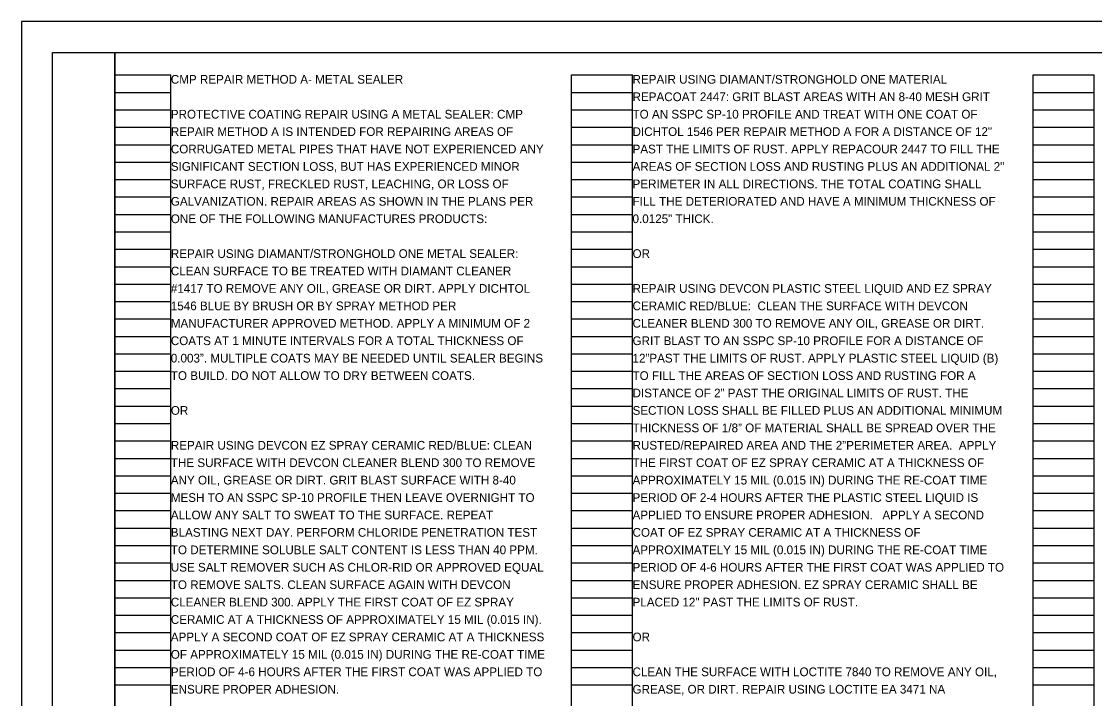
# Model space of a CAD drawing. Extents: x 0 to 34, y -22.7 to 22.
# Drawn here: x 0 to 17.24, y 11.12 to 22 of the extents above; entities that cross this region are included whole.
import ezdxf

# ---------------------------------------------------------------- set-up
doc = ezdxf.new("R2010")
doc.units = 0
for name, color, linetype in [('SH_Border', 7, 'Continuous'), ('SH_Cut_Line', 7, 'Continuous'), ('SH_Data', 7, 'Continuous'), ('SH_Text', 7, 'Continuous')]:
    doc.layers.add(name, color=color, linetype=linetype)

msp = doc.modelspace()

# ---------------------------------------------------------------- linework, layer by layer
at = {"layer": 'SH_Border'}
for points in [[(0.5, 21.5), (1.5, 21.5), (1.5, 0.5), (0.5, 0.5)], [(1.5, 21.5), (33.5, 21.5), (33.5, 0.5), (1.5, 0.5)]]:
    msp.add_lwpolyline(points, close=True, dxfattribs=at)
at = {"layer": 'SH_Cut_Line'}
msp.add_lwpolyline([(0, 0), (34, 0), (34, 22), (0, 22)], close=True, dxfattribs=at)
at = {"layer": 'SH_Data'}
for p, q in [((1.5, 0.98), (1.5, 21.14)), ((1.5, 21.14), (2.4, 21.14)), ((2.4, 0.98), (2.4, 21.14)), ((8.84, 0.98), (8.84, 21.14)), ((8.84, 21.14), (9.82, 21.14)), ((9.82, 0.98), (9.82, 21.14)), ((16.26, 0.98), (16.26, 21.14)), ((16.26, 21.14), (17.24, 21.14)), ((17.24, 0.98), (17.24, 21.14)), ((1.5, 20.86), (2.4, 20.86)), ((8.84, 20.86), (9.82, 20.86)), ((16.26, 20.86), (17.24, 20.86)), ((1.5, 20.58), (2.4, 20.58)), ((8.84, 20.58), (9.82, 20.58)), ((16.26, 20.58), (17.24, 20.58)), ((1.5, 20.3), (2.4, 20.3)), ((8.84, 20.3), (9.82, 20.3)), ((16.26, 20.3), (17.24, 20.3)), ((1.5, 20.02), (2.4, 20.02)), ((8.84, 20.02), (9.82, 20.02)), ((16.26, 20.02), (17.24, 20.02)), ((1.5, 19.74), (2.4, 19.74)), ((8.84, 19.74), (9.82, 19.74)), ((16.26, 19.74), (17.24, 19.74)), ((1.5, 19.46), (2.4, 19.46)), ((8.84, 19.46), (9.82, 19.46)), ((16.26, 19.46), (17.24, 19.46)), ((1.5, 19.18), (2.4, 19.18)), ((8.84, 19.18), (9.82, 19.18)), ((16.26, 19.18), (17.24, 19.18)), ((1.5, 18.9), (2.4, 18.9)), ((8.84, 18.9), (9.82, 18.9)), ((16.26, 18.9), (17.24, 18.9)), ((1.5, 18.62), (2.4, 18.62)), ((8.84, 18.62), (9.82, 18.62)), ((16.26, 18.62), (17.24, 18.62)), ((1.5, 18.34), (2.4, 18.34)), ((8.84, 18.34), (9.82, 18.34)), ((16.26, 18.34), (17.24, 18.34)), ((1.5, 18.06), (2.4, 18.06)), ((8.84, 18.06), (9.82, 18.06)), ((16.26, 18.06), (17.24, 18.06)), ((1.5, 17.78), (2.4, 17.78)), ((8.84, 17.78), (9.82, 17.78)), ((16.26, 17.78), (17.24, 17.78)), ((1.5, 17.5), (2.4, 17.5)), ((8.84, 17.5), (9.82, 17.5)), ((16.26, 17.5), (17.24, 17.5)), ((1.5, 17.22), (2.4, 17.22)), ((8.84, 17.22), (9.82, 17.22)), ((16.26, 17.22), (17.24, 17.22)), ((1.5, 16.94), (2.4, 16.94)), ((8.84, 16.94), (9.82, 16.94)), ((16.26, 16.94), (17.24, 16.94)), ((1.5, 16.66), (2.4, 16.66)), ((8.84, 16.66), (9.82, 16.66)), ((16.26, 16.66), (17.24, 16.66)), ((1.5, 16.38), (2.4, 16.38)), ((8.84, 16.38), (9.82, 16.38)), ((16.26, 16.38), (17.24, 16.38)), ((1.5, 16.1), (2.4, 16.1)), ((8.84, 16.1), (9.82, 16.1)), ((16.26, 16.1), (17.24, 16.1)), ((1.5, 15.82), (2.4, 15.82)), ((8.84, 15.82), (9.82, 15.82)), ((16.26, 15.82), (17.24, 15.82)), ((1.5, 15.54), (2.4, 15.54)), ((8.84, 15.54), (9.82, 15.54)), ((16.26, 15.54), (17.24, 15.54)), ((1.5, 15.26), (2.4, 15.26)), ((8.84, 15.26), (9.82, 15.26)), ((16.26, 15.26), (17.24, 15.26)), ((1.5, 14.98), (2.4, 14.98)), ((8.84, 14.98), (9.82, 14.98)), ((16.26, 14.98), (17.24, 14.98)), ((1.5, 14.7), (2.4, 14.7)), ((8.84, 14.7), (9.82, 14.7)), ((16.26, 14.7), (17.24, 14.7)), ((1.5, 14.42), (2.4, 14.42)), ((8.84, 14.42), (9.82, 14.42)), ((16.26, 14.42), (17.24, 14.42)), ((1.5, 14.14), (2.4, 14.14)), ((8.84, 14.14), (9.82, 14.14)), ((16.26, 14.14), (17.24, 14.14)), ((1.5, 13.86), (2.4, 13.86)), ((8.84, 13.86), (9.82, 13.86)), ((16.26, 13.86), (17.24, 13.86)), ((1.5, 13.58), (2.4, 13.58)), ((8.84, 13.58), (9.82, 13.58)), ((16.26, 13.58), (17.24, 13.58)), ((1.5, 13.3), (2.4, 13.3)), ((8.84, 13.3), (9.82, 13.3)), ((16.26, 13.3), (17.24, 13.3)), ((1.5, 13.02), (2.4, 13.02)), ((8.84, 13.02), (9.82, 13.02)), ((16.26, 13.02), (17.24, 13.02)), ((1.5, 12.74), (2.4, 12.74)), ((8.84, 12.74), (9.82, 12.74)), ((16.26, 12.74), (17.24, 12.74)), ((1.5, 12.46), (2.4, 12.46)), ((8.84, 12.46), (9.82, 12.46)), ((16.26, 12.46), (17.24, 12.46)), ((1.5, 12.18), (2.4, 12.18)), ((8.84, 12.18), (9.82, 12.18)), ((16.26, 12.18), (17.24, 12.18)), ((1.5, 11.9), (2.4, 11.9)), ((8.84, 11.9), (9.82, 11.9)), ((16.26, 11.9), (17.24, 11.9)), ((1.5, 11.62), (2.4, 11.62)), ((8.84, 11.62), (9.82, 11.62)), ((16.26, 11.62), (17.24, 11.62)), ((1.5, 11.34), (2.4, 11.34)), ((8.84, 11.34), (9.82, 11.34)), ((16.26, 11.34), (17.24, 11.34))]:
    msp.add_line(p, q, dxfattribs=at)

# ---------------------------------------------------------------- texts
at = {"layer": 'SH_Text'}
for s, p in [('CMP REPAIR METHOD A- METAL SEALER', (2.4, 21)), ('REPAIR USING DIAMANT/STRONGHOLD ONE MATERIAL ', (9.82, 21)), ('REPACOAT 2447: GRIT BLAST AREAS WITH AN 8-40 MESH GRIT ', (9.82, 20.72)), ('PROTECTIVE COATING REPAIR USING A METAL SEALER: CMP ', (2.4, 20.44)), ('TO AN SSPC SP-10 PROFILE AND TREAT WITH ONE COAT OF ', (9.82, 20.44)), ('REPAIR METHOD A IS INTENDED FOR REPAIRING AREAS OF ', (2.4, 20.16)), ('DICHTOL 1546 PER REPAIR METHOD A FOR A DISTANCE OF 12" ', (9.82, 20.16)), ('CORRUGATED METAL PIPES THAT HAVE NOT EXPERIENCED ANY ', (2.4, 19.88)), ('PAST THE LIMITS OF RUST. APPLY REPACOUR 2447 TO FILL THE ', (9.82, 19.88)), ('SIGNIFICANT SECTION LOSS, BUT HAS EXPERIENCED MINOR ', (2.4, 19.6)), ('AREAS OF SECTION LOSS AND RUSTING PLUS AN ADDITIONAL 2" ', (9.82, 19.6)), ('SURFACE RUST, FRECKLED RUST, LEACHING, OR LOSS OF ', (2.4, 19.32)), ('PERIMETER IN ALL DIRECTIONS. THE TOTAL COATING SHALL ', (9.82, 19.32)), ('GALVANIZATION. REPAIR AREAS AS SHOWN IN THE PLANS PER ', (2.4, 19.04)), ('FILL THE DETERIORATED AND HAVE A MINIMUM THICKNESS OF ', (9.82, 19.04)), ('ONE OF THE FOLLOWING MANUFACTURES PRODUCTS:', (2.4, 18.76)), ('0.0125" THICK.', (9.82, 18.76)), ('REPAIR USING DIAMANT/STRONGHOLD ONE METAL SEALER: ', (2.4, 18.2)), ('OR', (9.82, 18.2)), ('CLEAN SURFACE TO BE TREATED WITH DIAMANT CLEANER ', (2.4, 17.92)), ('#1417 TO REMOVE ANY OIL, GREASE OR DIRT. APPLY DICHTOL ', (2.4, 17.64)), ('REPAIR USING DEVCON PLASTIC STEEL LIQUID AND EZ SPRAY ', (9.82, 17.64)), ('1546 BLUE BY BRUSH OR BY SPRAY METHOD PER ', (2.4, 17.36)), ('CERAMIC RED/BLUE: \xa0CLEAN THE SURFACE WITH DEVCON ', (9.82, 17.36)), ('MANUFACTURER APPROVED METHOD. APPLY A MINIMUM OF 2 ', (2.4, 17.08)), ('CLEANER BLEND 300 TO REMOVE ANY OIL, GREASE OR DIRT.\xa0', (9.82, 17.08)), ('COATS AT 1 MINUTE INTERVALS FOR A TOTAL THICKNESS OF ', (2.4, 16.8)), ('GRIT BLAST TO AN SSPC SP-10 PROFILE FOR A DISTANCE OF ', (9.82, 16.8)), ('0.003”. MULTIPLE COATS MAY BE NEEDED UNTIL SEALER BEGINS ', (2.4, 16.52)), ('12”PAST THE LIMITS OF RUST. APPLY\xa0PLASTIC STEEL LIQUID (B)\xa0', (9.82, 16.52)), ('TO BUILD. DO NOT ALLOW TO DRY BETWEEN COATS. ', (2.4, 16.24)), ('TO FILL THE AREAS OF SECTION LOSS AND RUSTING FOR A ', (9.82, 16.24)), ('DISTANCE OF 2” PAST THE ORIGINAL LIMITS OF RUST. THE ', (9.82, 15.96)), ('OR', (2.4, 15.68)), ('SECTION LOSS SHALL BE FILLED PLUS AN ADDITIONAL MINIMUM ', (9.82, 15.68)), ('THICKNESS OF\xa01/8”\xa0OF MATERIAL SHALL BE SPREAD OVER THE ', (9.82, 15.4)), ('REPAIR USING DEVCON EZ SPRAY CERAMIC RED/BLUE: CLEAN ', (2.4, 15.12)), ('RUSTED/REPAIRED AREA AND THE 2”PERIMETER AREA. \xa0APPLY ', (9.82, 15.12)), ('THE SURFACE WITH DEVCON CLEANER BLEND 300 TO REMOVE ', (2.4, 14.84)), ('THE FIRST COAT OF\xa0EZ SPRAY CERAMIC AT A THICKNESS OF ', (9.82, 14.84)), ('ANY OIL, GREASE OR DIRT. GRIT BLAST SURFACE WITH 8-40 ', (2.4, 14.56)), ('APPROXIMATELY 15 MIL (0.015 IN) DURING THE RE-COAT TIME ', (9.82, 14.56)), ('MESH TO AN SSPC SP-10 PROFILE THEN LEAVE OVERNIGHT TO ', (2.4, 14.28)), ('PERIOD\xa0OF 2-4 HOURS\xa0AFTER\xa0THE PLASTIC STEEL LIQUID IS ', (9.82, 14.28)), ('ALLOW ANY SALT TO SWEAT TO THE SURFACE. REPEAT ', (2.4, 14)), ('APPLIED TO ENSURE PROPER ADHESION.\xa0 \xa0APPLY A SECOND ', (9.82, 14)), ('BLASTING NEXT DAY. PERFORM CHLORIDE PENETRATION TEST ', (2.4, 13.72)), ('COAT OF EZ SPRAY CERAMIC AT A THICKNESS OF ', (9.82, 13.72)), ('TO DETERMINE SOLUBLE SALT CONTENT IS LESS THAN 40 PPM. ', (2.4, 13.44)), ('APPROXIMATELY 15 MIL (0.015 IN) DURING THE\xa0RE-COAT\xa0TIME ', (9.82, 13.44)), ('USE SALT REMOVER SUCH AS CHLOR-RID OR APPROVED EQUAL ', (2.4, 13.16)), ('PERIOD OF 4-6 HOURS AFTER THE FIRST COAT WAS APPLIED TO ', (9.82, 13.16)), ('TO REMOVE SALTS. CLEAN SURFACE AGAIN WITH DEVCON ', (2.4, 12.88)), ('ENSURE PROPER ADHESION. EZ SPRAY CERAMIC SHALL BE ', (9.82, 12.88)), ('CLEANER BLEND 300.\xa0APPLY THE FIRST COAT OF\xa0EZ SPRAY ', (2.4, 12.6)), ('PLACED 12" PAST THE LIMITS OF RUST.', (9.82, 12.6)), ('CERAMIC AT A THICKNESS OF APPROXIMATELY 15 MIL (0.015 IN). \xa0', (2.4, 12.32)), ('APPLY A SECOND COAT OF EZ SPRAY CERAMIC AT A THICKNESS ', (2.4, 12.04)), ('OR', (9.82, 12.04)), ('OF APPROXIMATELY 15 MIL (0.015 IN) DURING THE\xa0RE-COAT\xa0TIME ', (2.4, 11.76)), ('PERIOD OF 4-6 HOURS AFTER THE FIRST COAT WAS APPLIED TO ', (2.4, 11.48)), ('CLEAN THE SURFACE WITH LOCTITE 7840 TO REMOVE ANY OIL, ', (9.82, 11.48)), ('ENSURE PROPER ADHESION.', (2.4, 11.2)), ('GREASE, OR DIRT. REPAIR USING LOCTITE EA 3471 NA ', (9.82, 11.2))]:
    msp.add_text(s, height=0.14, dxfattribs=at).set_placement(p)

doc.saveas('drawing.dxf')
